(* Logix 5000 project; controller eNod4TSample vendor 1 type 14 code 106 rev 28.12; software revision 28.00 *)

TASK MainTask (continuous, watchdog 500 ms) : MainProgram

MODULES
   Local : vendor 1 type 14 code 106 (Compact 0, rev 28.12)
      Scale1 : vendor 1354 type 100 code 100 (Ethernet 192.168.0.100, rev 2.1, StandardDataDriven RPI 20 ms)
END_MODULES

TYPE TeNod4TCAL :   // Calibration datas class 0x65
STRUCT
   MeasureRange : DINT;
   CalibSegments : INT;
   CalibSegment1 : DINT;
   CalibSegment2 : DINT;
   CalibSegment3 : DINT;
   SensorSens : DINT;
   Step : INT;
   CalibZero : DINT;
   CalibCoeff1 : REAL;
   CalibCoeff2 : REAL;
   CalibCoeff3 : REAL;
   CalibSpanCorr : DINT;
   gValueCalib : DINT;
   gValueLocal : DINT;
   ZeroOffset : DINT;
   FixedTare : DINT;
   SensorRef : DINT;
   SensorTol : INT;
END_STRUCT
END_TYPE

TYPE TeNod4TCYCIN :
STRUCT
   eNodCounter : DINT;
   MeasureStatus : TeNod4TStatus;
   Gross : DINT;
   Tare : DINT;
   Net : DINT;
   ADCPoints : DINT;
   CommandEcho : INT;
   Response : INT;
END_STRUCT
END_TYPE

TYPE TeNod4TCYCOUT :
STRUCT
   Command : INT;
END_STRUCT
END_TYPE

TYPE TeNod4TDatas :   // Global datas for eNod4 and functions
STRUCT
   CYCIN : TeNod4TCYCIN;
   CYCOUT : TeNod4TCYCOUT;
   CAL : TeNod4TCAL;
   FIL : TeNod4TFILTER;
   LEGAL : TeNod4TLEGAL;
   IOCFG : TeNod4TIOCFG;
   MSGBuffer : SINT[100];   // Internaly used for explicit messages
   MSGGroup : INT;   // Current message group of last comm error
   MSGClass : INT;   // Current CIP class of last comm error
   MSGAttribute : INT;   // Current CIP attribute of last comm error
   MSGError : INT;   // Last MSG error
   MSGErrorEx : DINT;   // Last MSG extendeed error
   INT : TeNod4TInternal;   // Internal usage
END_STRUCT
END_TYPE

TYPE TeNod4TFILTER :
STRUCT
   ADConversionRate : INT;
   Activation : SINT;
   LowPassOrder : SINT;
   LowPassFreq : INT;
   BandCutHigh : INT;
   BandCutLow : INT;
END_STRUCT
END_TYPE

TYPE TeNod4TInternal :   // For internal usage between blocs, do not use
STRUCT
   CALRead : BOOL;
   CALWrite : BOOL;
   FILTERRead : BOOL;
   FILTERWrite : BOOL;
   CalibWrite : BOOL;
   LegelReadAll : BOOL;
   LegalWriteCfg : BOOL;
   LegalReadLastID : BOOL;
   LegalReadDSD : BOOL;
   LegalWriteID : BOOL;
   IOCFGRead : BOOL;
   IOCFGWrite : BOOL;
   Ready : BOOL;
   Done : BOOL;
   Error : BOOL;
   MSGError : BOOL;
   MSGCancel : BOOL;
   Command : INT;
END_STRUCT
END_TYPE

TYPE TeNod4TIOCFG :
STRUCT
   Input1Function : SINT;
   Input2Function : SINT;
   HoldingTime : INT;
   Output1Function : SINT;
   Output2Function : SINT;
   Output3Function : SINT;
   Output4Function : SINT;
   SetPoint1High : DINT;
   SetPoint1Low : DINT;
   SetPoint2High : DINT;
   SetPoint2Low : DINT;
   SetPoint3High : DINT;
   SetPoint3Low : DINT;
   SetPoint4High : DINT;
   SetPoint4Low : DINT;
   Setpoint12Function : SINT;
   Setpoint34Function : SINT;
END_STRUCT
END_TYPE

TYPE TeNod4TLEGAL :
STRUCT
   eNodVersion : INT;
   ModbusCfg : INT;
   LegalVersion : SINT;
   LegalSwitch : SINT;
   LegalCount : SINT;
   LegalChecksum : INT;
   ZeroConfig : INT;
   Stability : SINT;
   Decimal : SINT;
   Unit : SINT[4];
   DSDLastID : DINT;
   DSDOldestID : DINT;
   DSDCurrentID : DINT;
   DSDReadID : DINT;
   DSDReadNet : DINT;
   DSDResdTare : DINT;
   DSDReadStatus : INT;
   DSDReadChecksum : INT;
   HMIName : SINT[4];
END_STRUCT
END_TYPE

TYPE TeNod4TMSGElement :   // Internal use
STRUCT
   Class : SINT;
   Attribute : SINT;
   Offset : SINT;
   Length : SINT;
END_STRUCT
END_TYPE

TYPE TeNod4TStatus :
STRUCT
   Reserved : INT;
   b00Reserved : BOOL;
   b01Reserved : BOOL;
   b02ErrorCode0 : BOOL;
   b03ErrorCode1 : BOOL;
   b04NoMotion : BOOL;
   b05ZeroWeight : BOOL;
   b06EEPROMFailure : BOOL;
   b07Reserved : BOOL;
   b08Input1ON : BOOL;
   b09Input2ON : BOOL;
   b10Output1ON : BOOL;
   b11Output2ON : BOOL;
   b12Output3ON : BOOL;
   b13Output4ON : BOOL;
   b14TareActive : BOOL;
   b15Reservd : BOOL;
END_STRUCT
END_TYPE

ADD_ON_INSTRUCTION TeNod4TBlocBackupRestore   (* revision 1.1, vendor Scaime *)
VAR_IN_OUT
   Datas : TeNod4TDatas; {required}
END_VAR
VAR_INPUT
   Backup : BOOL; {visible}
   Restore : BOOL; {visible}
END_VAR
VAR_OUTPUT
   InProgress : BOOL; {visible}
   Done : BOOL; {visible}
   Error : BOOL; {visible}
END_VAR
VAR
   IntBackup : BOOL; {access None}
   IntRestore1 : BOOL; {access None}
   IntRestore2 : BOOL; {access None}
   IntRestore3 : BOOL; {access None}
   IntRestore4 : BOOL; {access None}
END_VAR

ROUTINE Logic   (* ladder *)
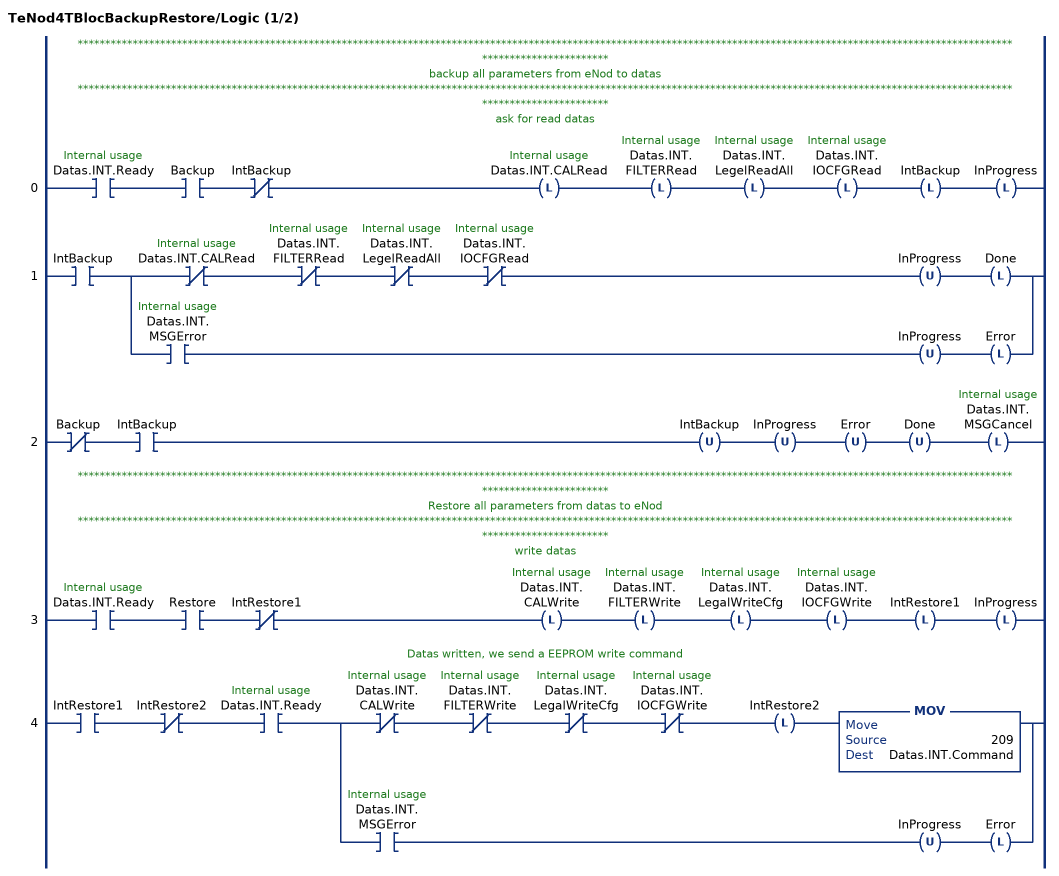
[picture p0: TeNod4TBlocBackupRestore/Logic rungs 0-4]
   // *************************************************************************************************************************************************************************************************
   // backup all parameters from eNod to datas
   // *************************************************************************************************************************************************************************************************
   // ask for read datas
   0: XIC(Datas.INT.Ready)XIC(Backup)XIO(IntBackup)OTL(Datas.INT.CALRead)OTL(Datas.INT.FILTERRead)OTL(Datas.INT.LegelReadAll)OTL(Datas.INT.IOCFGRead)OTL(IntBackup)OTL(InProgress);
   1: XIC(IntBackup)[XIO(Datas.INT.CALRead) XIO(Datas.INT.FILTERRead) XIO(Datas.INT.LegelReadAll) XIO(Datas.INT.IOCFGRead) OTU(InProgress) OTL(Done) ,XIC(Datas.INT.MSGError) OTU(InProgress) OTL(Error) ];
   2: XIO(Backup)XIC(IntBackup)OTU(IntBackup)OTU(InProgress)OTU(Error)OTU(Done)OTL(Datas.INT.MSGCancel);
   // *************************************************************************************************************************************************************************************************
   // Restore all parameters from datas to eNod
   // *************************************************************************************************************************************************************************************************
   // write datas
   3: XIC(Datas.INT.Ready)XIC(Restore)XIO(IntRestore1)OTL(Datas.INT.CALWrite)OTL(Datas.INT.FILTERWrite)OTL(Datas.INT.LegalWriteCfg)OTL(Datas.INT.IOCFGWrite)OTL(IntRestore1)OTL(InProgress);
   // Datas written, we send a EEPROM write command
   4: XIC(IntRestore1)XIO(IntRestore2)XIC(Datas.INT.Ready)[XIO(Datas.INT.CALWrite) XIO(Datas.INT.FILTERWrite) XIO(Datas.INT.LegalWriteCfg) XIO(Datas.INT.IOCFGWrite) OTL(IntRestore2) MOV(209,Datas.INT.Command) ,XIC(Datas.INT.MSGError) OTU(InProgress) OTL(Error) ];
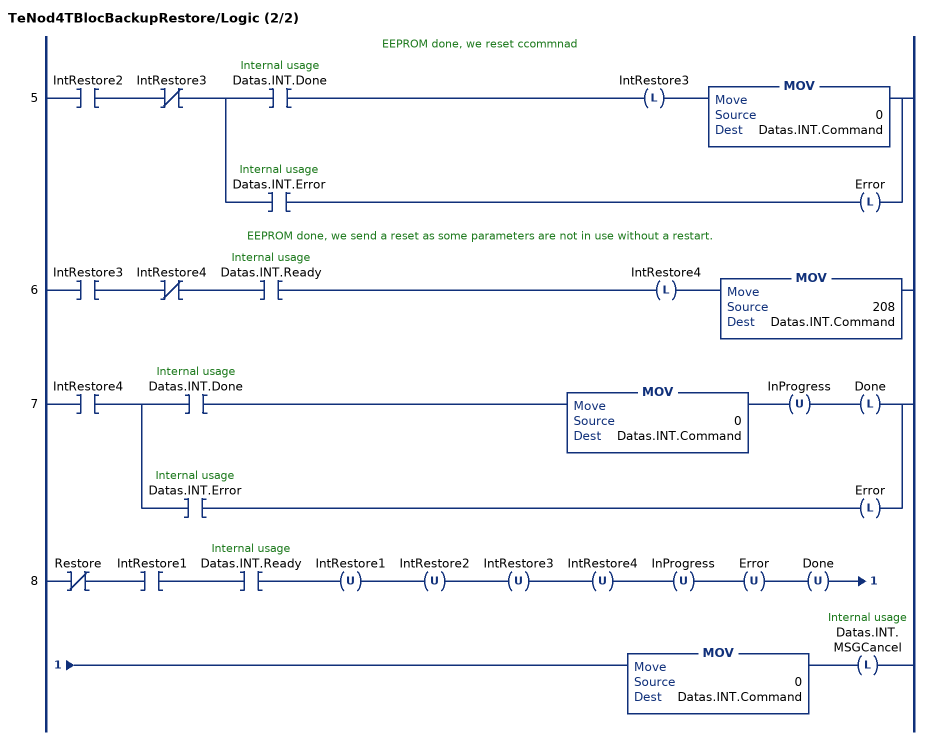
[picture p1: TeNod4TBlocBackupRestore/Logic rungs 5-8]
   // EEPROM done, we reset ccommnad
   5: XIC(IntRestore2)XIO(IntRestore3)[XIC(Datas.INT.Done) OTL(IntRestore3) MOV(0,Datas.INT.Command) ,XIC(Datas.INT.Error) OTL(Error) ];
   // EEPROM done, we send a reset as some parameters are not in use without a restart.
   6: XIC(IntRestore3)XIO(IntRestore4)XIC(Datas.INT.Ready)OTL(IntRestore4)MOV(208,Datas.INT.Command);
   7: XIC(IntRestore4)[XIC(Datas.INT.Done) MOV(0,Datas.INT.Command) OTU(InProgress) OTL(Done) ,XIC(Datas.INT.Error) OTL(Error) ];
   8: XIO(Restore)XIC(IntRestore1)XIC(Datas.INT.Ready)OTU(IntRestore1)OTU(IntRestore2)OTU(IntRestore3)OTU(IntRestore4)OTU(InProgress)OTU(Error)OTU(Done)MOV(0,Datas.INT.Command)OTL(Datas.INT.MSGCancel);
END_ROUTINE
END_ADD_ON_INSTRUCTION

ADD_ON_INSTRUCTION TeNod4TBlocCalibration   (* revision 1.0, vendor Scaime *)
VAR_IN_OUT
   Datas : TeNod4TDatas; {required}
END_VAR
VAR_INPUT
   NumSegment : INT := 1; {visible}
   ValSegment1 : DINT; {visible}
   ValSegment2 : DINT; {visible}
   ValSegment3 : DINT; {visible}
   Start : BOOL; {visible}
   Zero : BOOL; {visible}
   Segment1 : BOOL; {visible}
   Segment2 : BOOL; {visible}
   Segment3 : BOOL; {visible}
   Save : BOOL; {visible}
   Cancel : BOOL; {visible}
   Theorical : BOOL; {visible}
   ZeroAdjust : BOOL; {visible}
END_VAR
VAR_OUTPUT
   InProgress : BOOL; {visible}
   ZeroDone : BOOL; {visible}
   Seg1Done : BOOL; {visible}
   Seg2Done : BOOL; {visible}
   Seg3Done : BOOL; {visible}
   Complete : BOOL; {visible}
   Error : BOOL; {visible}
END_VAR
VAR
   IntStart1 : BOOL; {access None}
   IntStart2 : BOOL; {access None}
   IntZero : BOOL; {access None}
   IntSeg1 : BOOL; {access None}
   IntSeg2 : BOOL; {access None}
   IntSeg3 : BOOL; {access None}
   IntSave1 : BOOL; {access None}
   IntSave2 : BOOL; {access None}
   IntCancel : BOOL; {access None}
   IntTheo : BOOL; {access None}
   IntZeroA : BOOL; {access None}
   IntSeg1B : BOOL; {access None}
   IntSeg2B : BOOL; {access None}
   IntSeg3B : BOOL; {access None}
END_VAR

ROUTINE Logic   (* ladder *)
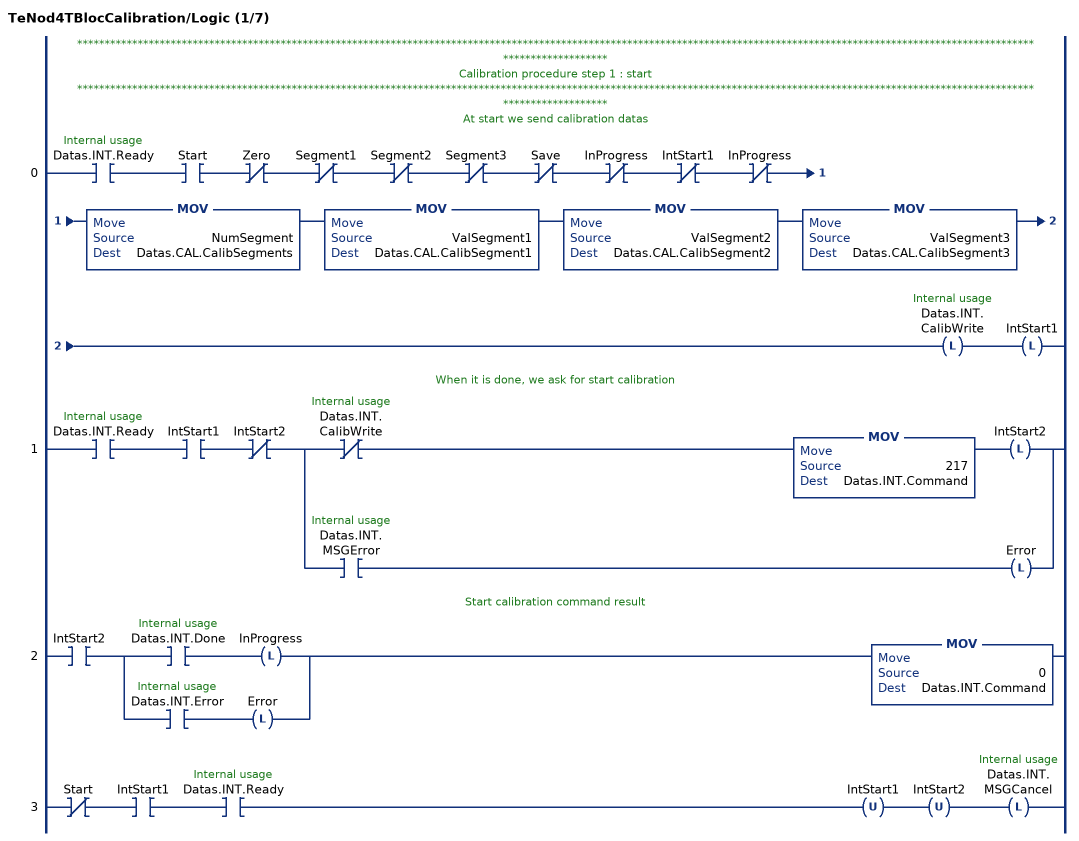
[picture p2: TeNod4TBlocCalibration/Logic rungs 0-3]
   // *************************************************************************************************************************************************************************************************
   // Calibration procedure step 1 : start
   // *************************************************************************************************************************************************************************************************
   // At start we send calibration datas
   0: XIC(Datas.INT.Ready)XIC(Start)XIO(Zero)XIO(Segment1)XIO(Segment2)XIO(Segment3)XIO(Save)XIO(InProgress)XIO(IntStart1)XIO(InProgress)MOV(NumSegment,Datas.CAL.CalibSegments)MOV(ValSegment1,Datas.CAL.CalibSegment1)MOV(ValSegment2,Datas.CAL.CalibSegment2)MOV(ValSegment3,Datas.CAL.CalibSegment3)OTL(Datas.INT.CalibWrite)OTL(IntStart1);
   // When it is done, we ask for start calibration
   1: XIC(Datas.INT.Ready)XIC(IntStart1)XIO(IntStart2)[XIO(Datas.INT.CalibWrite) MOV(217,Datas.INT.Command) OTL(IntStart2) ,XIC(Datas.INT.MSGError) OTL(Error) ];
   // Start calibration command result
   2: XIC(IntStart2)[XIC(Datas.INT.Done) OTL(InProgress) ,XIC(Datas.INT.Error) OTL(Error) ]MOV(0,Datas.INT.Command);
   3: XIO(Start)XIC(IntStart1)XIC(Datas.INT.Ready)OTU(IntStart1)OTU(IntStart2)OTL(Datas.INT.MSGCancel);
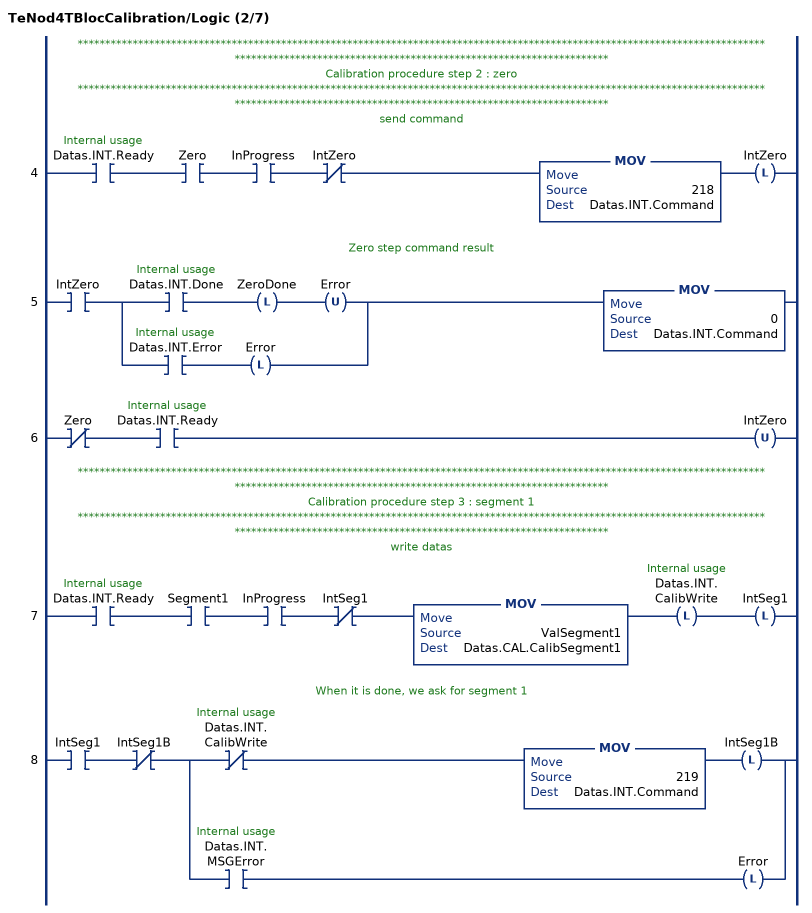
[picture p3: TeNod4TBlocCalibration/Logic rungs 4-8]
   // *************************************************************************************************************************************************************************************************
   // Calibration procedure step 2 : zero
   // *************************************************************************************************************************************************************************************************
   // send command
   4: XIC(Datas.INT.Ready)XIC(Zero)XIC(InProgress)XIO(IntZero)MOV(218,Datas.INT.Command)OTL(IntZero);
   // Zero step command result
   5: XIC(IntZero)[XIC(Datas.INT.Done) OTL(ZeroDone) OTU(Error) ,XIC(Datas.INT.Error) OTL(Error) ]MOV(0,Datas.INT.Command);
   6: XIO(Zero)XIC(Datas.INT.Ready)OTU(IntZero);
   // *************************************************************************************************************************************************************************************************
   // Calibration procedure step 3 : segment 1
   // *************************************************************************************************************************************************************************************************
   // write datas
   7: XIC(Datas.INT.Ready)XIC(Segment1)XIC(InProgress)XIO(IntSeg1)MOV(ValSegment1,Datas.CAL.CalibSegment1)OTL(Datas.INT.CalibWrite)OTL(IntSeg1);
   // When it is done, we ask for segment 1
   8: XIC(IntSeg1)XIO(IntSeg1B)[XIO(Datas.INT.CalibWrite) MOV(219,Datas.INT.Command) OTL(IntSeg1B) ,XIC(Datas.INT.MSGError) OTL(Error) ];
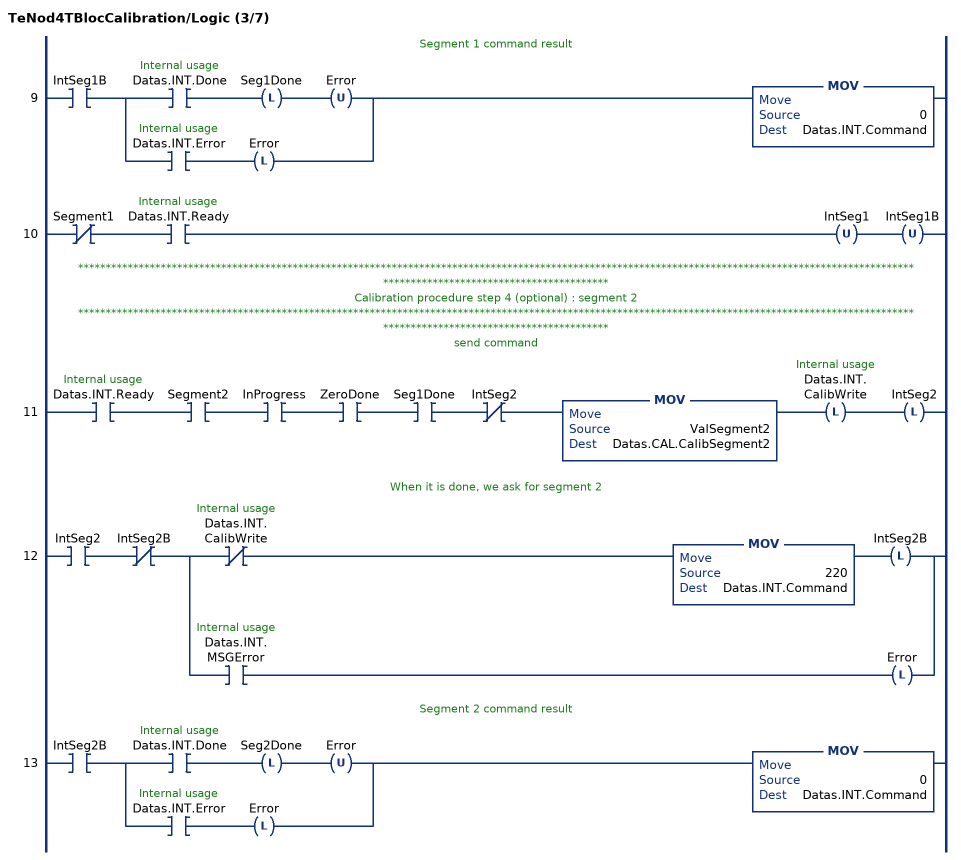
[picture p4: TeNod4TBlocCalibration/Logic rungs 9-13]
   // Segment 1 command result
   9: XIC(IntSeg1B)[XIC(Datas.INT.Done) OTL(Seg1Done) OTU(Error) ,XIC(Datas.INT.Error) OTL(Error) ]MOV(0,Datas.INT.Command);
   10: XIO(Segment1)XIC(Datas.INT.Ready)OTU(IntSeg1)OTU(IntSeg1B);
   // *************************************************************************************************************************************************************************************************
   // Calibration procedure step 4 (optional) : segment 2
   // *************************************************************************************************************************************************************************************************
   // send command
   11: XIC(Datas.INT.Ready)XIC(Segment2)XIC(InProgress)XIC(ZeroDone)XIC(Seg1Done)XIO(IntSeg2)MOV(ValSegment2,Datas.CAL.CalibSegment2)OTL(Datas.INT.CalibWrite)OTL(IntSeg2);
   // When it is done, we ask for segment 2
   12: XIC(IntSeg2)XIO(IntSeg2B)[XIO(Datas.INT.CalibWrite) MOV(220,Datas.INT.Command) OTL(IntSeg2B) ,XIC(Datas.INT.MSGError) OTL(Error) ];
   // Segment 2 command result
   13: XIC(IntSeg2B)[XIC(Datas.INT.Done) OTL(Seg2Done) OTU(Error) ,XIC(Datas.INT.Error) OTL(Error) ]MOV(0,Datas.INT.Command);
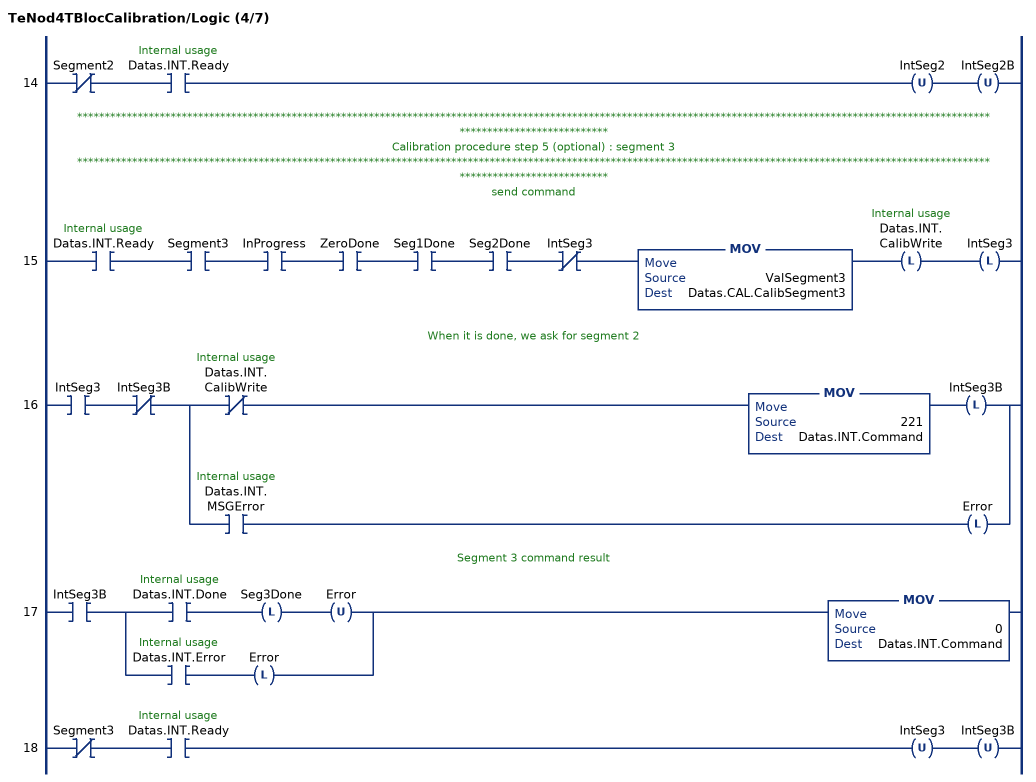
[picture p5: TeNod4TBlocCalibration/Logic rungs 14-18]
   14: XIO(Segment2)XIC(Datas.INT.Ready)OTU(IntSeg2)OTU(IntSeg2B);
   // *************************************************************************************************************************************************************************************************
   // Calibration procedure step 5 (optional) : segment 3
   // *************************************************************************************************************************************************************************************************
   // send command
   15: XIC(Datas.INT.Ready)XIC(Segment3)XIC(InProgress)XIC(ZeroDone)XIC(Seg1Done)XIC(Seg2Done)XIO(IntSeg3)MOV(ValSegment3,Datas.CAL.CalibSegment3)OTL(Datas.INT.CalibWrite)OTL(IntSeg3);
   // When it is done, we ask for segment 2
   16: XIC(IntSeg3)XIO(IntSeg3B)[XIO(Datas.INT.CalibWrite) MOV(221,Datas.INT.Command) OTL(IntSeg3B) ,XIC(Datas.INT.MSGError) OTL(Error) ];
   // Segment 3 command result
   17: XIC(IntSeg3B)[XIC(Datas.INT.Done) OTL(Seg3Done) OTU(Error) ,XIC(Datas.INT.Error) OTL(Error) ]MOV(0,Datas.INT.Command);
   18: XIO(Segment3)XIC(Datas.INT.Ready)OTU(IntSeg3)OTU(IntSeg3B);
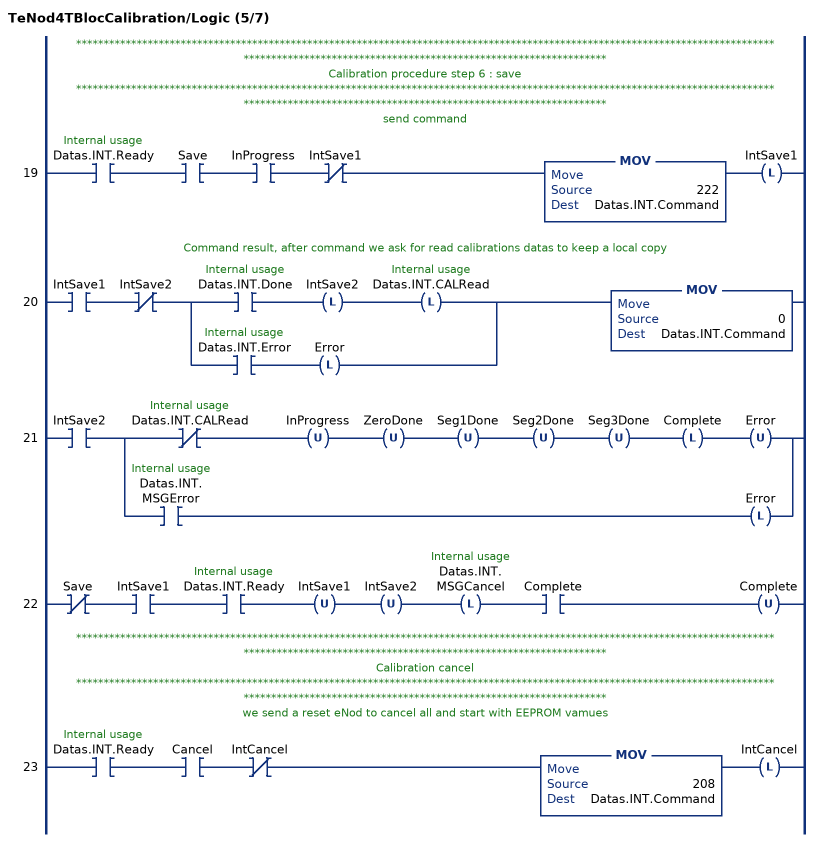
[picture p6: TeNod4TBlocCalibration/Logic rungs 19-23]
   // *************************************************************************************************************************************************************************************************
   // Calibration procedure step 6 : save
   // *************************************************************************************************************************************************************************************************
   // send command
   19: XIC(Datas.INT.Ready)XIC(Save)XIC(InProgress)XIO(IntSave1)MOV(222,Datas.INT.Command)OTL(IntSave1);
   // Command result, after command we ask for read calibrations datas to keep a local copy
   20: XIC(IntSave1)XIO(IntSave2)[XIC(Datas.INT.Done) OTL(IntSave2) OTL(Datas.INT.CALRead) ,XIC(Datas.INT.Error) OTL(Error) ]MOV(0,Datas.INT.Command);
   21: XIC(IntSave2)[XIO(Datas.INT.CALRead) OTU(InProgress) OTU(ZeroDone) OTU(Seg1Done) OTU(Seg2Done) OTU(Seg3Done) OTL(Complete) OTU(Error) ,XIC(Datas.INT.MSGError) OTL(Error) ];
   22: XIO(Save)XIC(IntSave1)XIC(Datas.INT.Ready)OTU(IntSave1)OTU(IntSave2)OTL(Datas.INT.MSGCancel)XIC(Complete)OTU(Complete);
   // *************************************************************************************************************************************************************************************************
   // Calibration cancel
   // *************************************************************************************************************************************************************************************************
   // we send a reset eNod to cancel all and start with EEPROM vamues
   23: XIC(Datas.INT.Ready)XIC(Cancel)XIO(IntCancel)MOV(208,Datas.INT.Command)OTL(IntCancel);
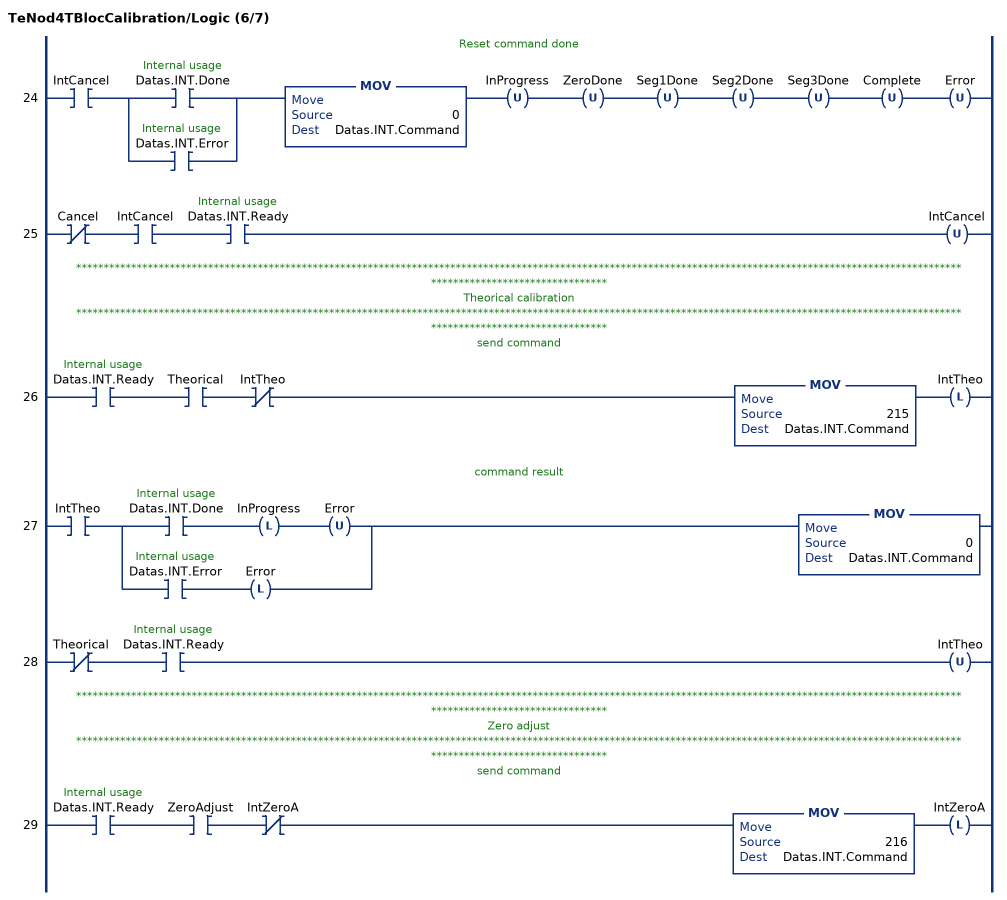
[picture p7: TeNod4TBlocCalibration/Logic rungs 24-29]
   // Reset command done
   24: XIC(IntCancel)[XIC(Datas.INT.Done) ,XIC(Datas.INT.Error) ]MOV(0,Datas.INT.Command)OTU(InProgress)OTU(ZeroDone)OTU(Seg1Done)OTU(Seg2Done)OTU(Seg3Done)OTU(Complete)OTU(Error);
   25: XIO(Cancel)XIC(IntCancel)XIC(Datas.INT.Ready)OTU(IntCancel);
   // *************************************************************************************************************************************************************************************************
   // Theorical calibration
   // *************************************************************************************************************************************************************************************************
   // send command
   26: XIC(Datas.INT.Ready)XIC(Theorical)XIO(IntTheo)MOV(215,Datas.INT.Command)OTL(IntTheo);
   // command result
   27: XIC(IntTheo)[XIC(Datas.INT.Done) OTL(InProgress) OTU(Error) ,XIC(Datas.INT.Error) OTL(Error) ]MOV(0,Datas.INT.Command);
   28: XIO(Theorical)XIC(Datas.INT.Ready)OTU(IntTheo);
   // *************************************************************************************************************************************************************************************************
   // Zero adjust
   // *************************************************************************************************************************************************************************************************
   // send command
   29: XIC(Datas.INT.Ready)XIC(ZeroAdjust)XIO(IntZeroA)MOV(216,Datas.INT.Command)OTL(IntZeroA);
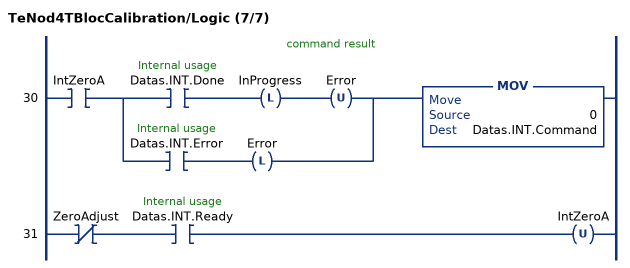
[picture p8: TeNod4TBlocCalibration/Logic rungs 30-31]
   // command result
   30: XIC(IntZeroA)[XIC(Datas.INT.Done) OTL(InProgress) OTU(Error) ,XIC(Datas.INT.Error) OTL(Error) ]MOV(0,Datas.INT.Command);
   31: XIO(ZeroAdjust)XIC(Datas.INT.Ready)OTU(IntZeroA);
END_ROUTINE
END_ADD_ON_INSTRUCTION

ADD_ON_INSTRUCTION TeNod4TBlocFilters   (* revision 1.1, vendor Scaime *)
VAR_IN_OUT
   Datas : TeNod4TDatas; {required}
END_VAR
VAR_INPUT
   Read : BOOL; {visible}
   Write : BOOL; {visible}
END_VAR
VAR_OUTPUT
   InProgress : BOOL; {visible}
   Done : BOOL; {visible}
   Error : BOOL; {visible}
END_VAR
VAR
   IntRead : BOOL; {access None}
   IntWrite1 : BOOL; {access None}
   IntWrite2 : BOOL; {access None}
END_VAR

ROUTINE Logic   (* ladder *)
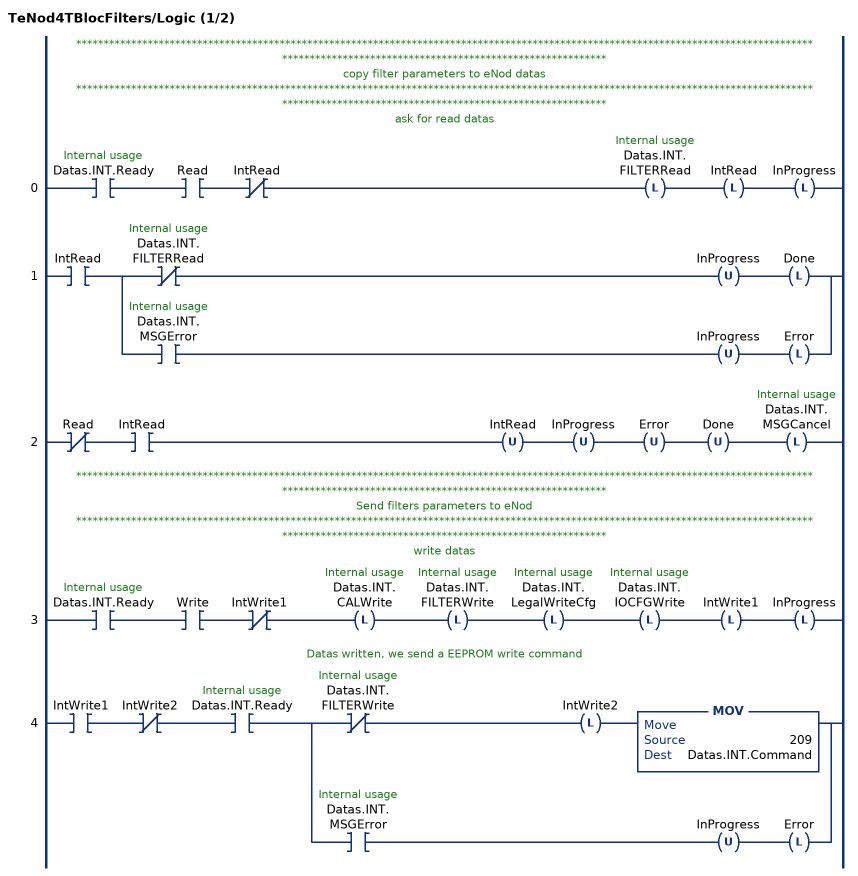
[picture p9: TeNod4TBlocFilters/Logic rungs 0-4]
   // *************************************************************************************************************************************************************************************************
   // copy filter parameters to eNod datas
   // *************************************************************************************************************************************************************************************************
   // ask for read datas
   0: XIC(Datas.INT.Ready)XIC(Read)XIO(IntRead)OTL(Datas.INT.FILTERRead)OTL(IntRead)OTL(InProgress);
   1: XIC(IntRead)[XIO(Datas.INT.FILTERRead) OTU(InProgress) OTL(Done) ,XIC(Datas.INT.MSGError) OTU(InProgress) OTL(Error) ];
   2: XIO(Read)XIC(IntRead)OTU(IntRead)OTU(InProgress)OTU(Error)OTU(Done)OTL(Datas.INT.MSGCancel);
   // *************************************************************************************************************************************************************************************************
   // Send filters parameters to eNod
   // *************************************************************************************************************************************************************************************************
   // write datas
   3: XIC(Datas.INT.Ready)XIC(Write)XIO(IntWrite1)OTL(Datas.INT.CALWrite)OTL(Datas.INT.FILTERWrite)OTL(Datas.INT.LegalWriteCfg)OTL(Datas.INT.IOCFGWrite)OTL(IntWrite1)OTL(InProgress);
   // Datas written, we send a EEPROM write command
   4: XIC(IntWrite1)XIO(IntWrite2)XIC(Datas.INT.Ready)[XIO(Datas.INT.FILTERWrite) OTL(IntWrite2) MOV(209,Datas.INT.Command) ,XIC(Datas.INT.MSGError) OTU(InProgress) OTL(Error) ];
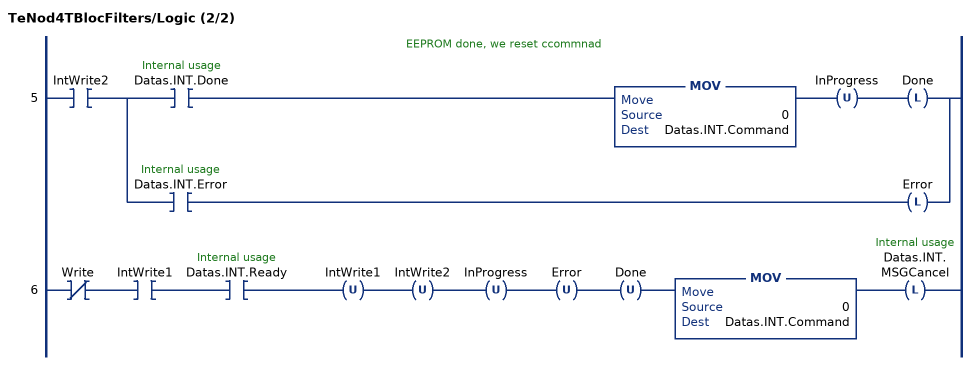
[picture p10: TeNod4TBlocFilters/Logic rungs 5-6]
   // EEPROM done, we reset ccommnad
   5: XIC(IntWrite2)[XIC(Datas.INT.Done) MOV(0,Datas.INT.Command) OTU(InProgress) OTL(Done) ,XIC(Datas.INT.Error) OTL(Error) ];
   6: XIO(Write)XIC(IntWrite1)XIC(Datas.INT.Ready)OTU(IntWrite1)OTU(IntWrite2)OTU(InProgress)OTU(Error)OTU(Done)MOV(0,Datas.INT.Command)OTL(Datas.INT.MSGCancel);
END_ROUTINE
END_ADD_ON_INSTRUCTION

ADD_ON_INSTRUCTION TeNod4TBlocLegal   (* revision 1.1, vendor Scaime *)
VAR_IN_OUT
   Datas : TeNod4TDatas; {required}
END_VAR
VAR_INPUT
   CaptureRead : BOOL; {visible}
   CaptureOnly : BOOL; {visible}
   RequestedID : DINT; {visible}
   Read : BOOL; {visible}
END_VAR
VAR_OUTPUT
   InProgress : BOOL; {visible}
   Done : BOOL; {visible}
   Error : BOOL; {visible}
   CapturedID : DINT; {access Read Only, visible}
END_VAR
VAR
   IntCapture1 : BOOL; {access None}
   IntCapture2 : BOOL; {access None}
   IntCapture3 : BOOL; {access None}
   ReadSeq : BOOL; {access None}
   ReadSeq1 : BOOL; {access None}
   ReadSeq2 : BOOL; {access None}
   ReadSeq3 : BOOL; {access None}
   ReadSeqDone : BOOL; {access None}
   IntRead1 : BOOL; {access None}
END_VAR

ROUTINE Logic   (* ladder *)
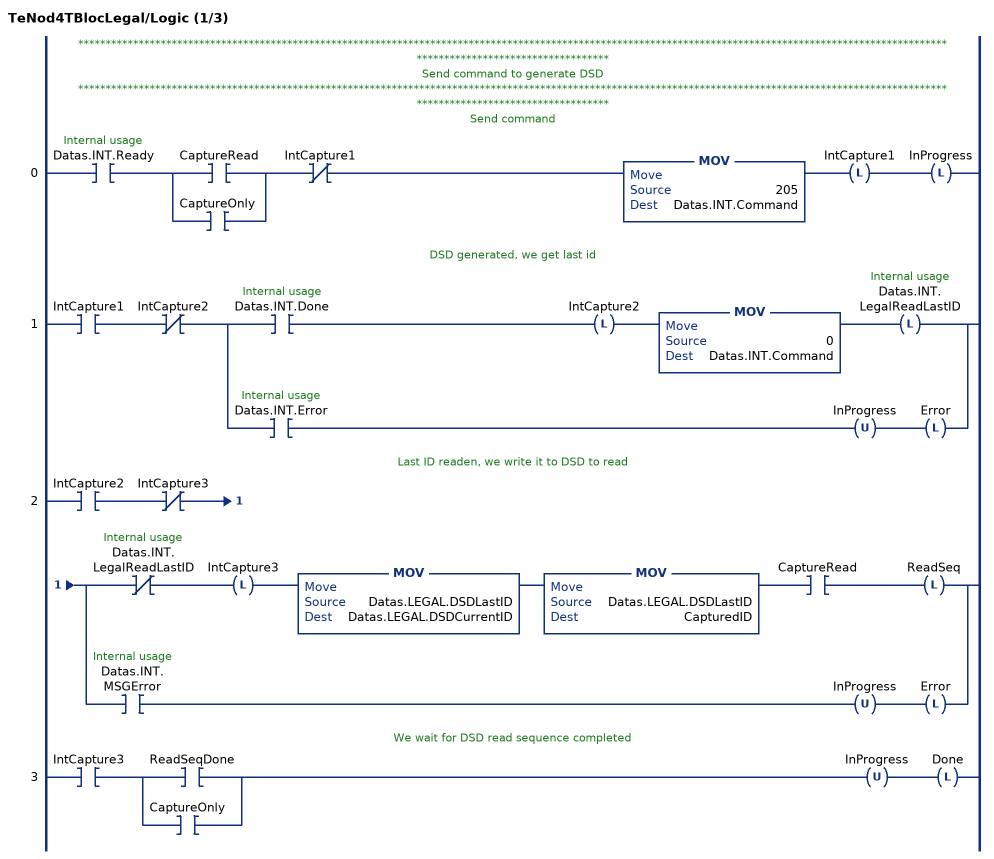
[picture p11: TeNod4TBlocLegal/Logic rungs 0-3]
   // *************************************************************************************************************************************************************************************************
   // Send command to generate DSD
   // *************************************************************************************************************************************************************************************************
   // Send command
   0: XIC(Datas.INT.Ready)[XIC(CaptureRead) ,XIC(CaptureOnly) ]XIO(IntCapture1)MOV(205,Datas.INT.Command)OTL(IntCapture1)OTL(InProgress);
   // DSD generated, we get last id
   1: XIC(IntCapture1)XIO(IntCapture2)[XIC(Datas.INT.Done) OTL(IntCapture2) MOV(0,Datas.INT.Command) OTL(Datas.INT.LegalReadLastID) ,XIC(Datas.INT.Error) OTU(InProgress) OTL(Error) ];
   // Last ID readen, we write it to DSD to read
   2: XIC(IntCapture2)XIO(IntCapture3)[XIO(Datas.INT.LegalReadLastID) OTL(IntCapture3) MOV(Datas.LEGAL.DSDLastID,Datas.LEGAL.DSDCurrentID) MOV(Datas.LEGAL.DSDLastID,CapturedID) XIC(CaptureRead) OTL(ReadSeq) ,XIC(Datas.INT.MSGError) OTU(InProgress) OTL(Error) ];
   // We wait for DSD read sequence completed
   3: XIC(IntCapture3)[XIC(ReadSeqDone) ,XIC(CaptureOnly) ]OTU(InProgress)OTL(Done);
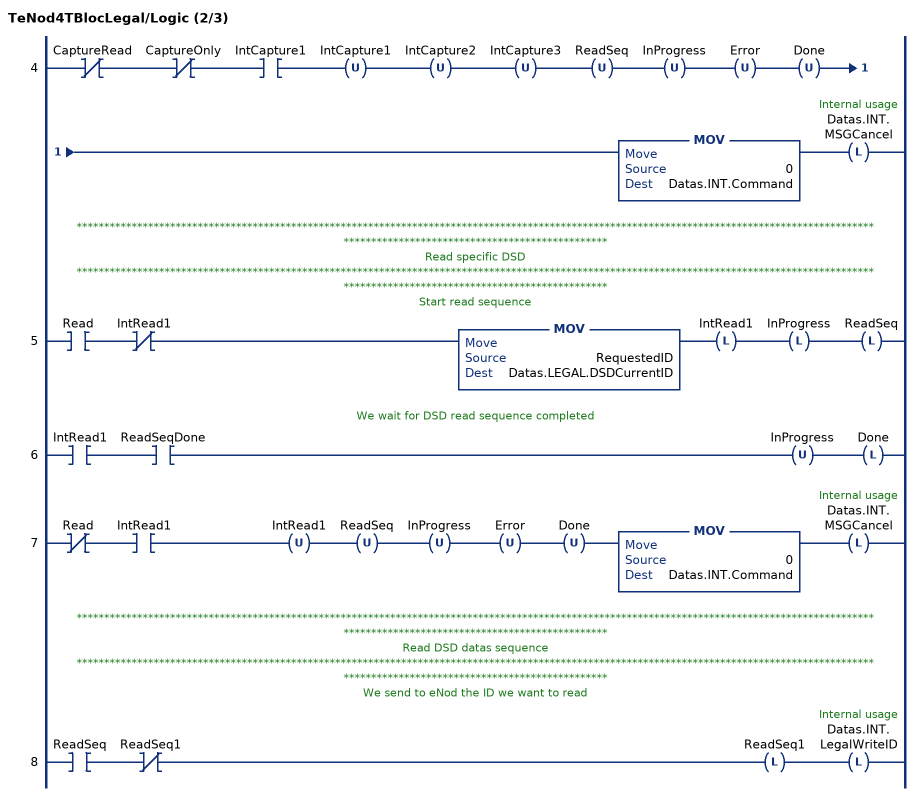
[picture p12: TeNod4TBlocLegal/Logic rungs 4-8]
   4: XIO(CaptureRead)XIO(CaptureOnly)XIC(IntCapture1)OTU(IntCapture1)OTU(IntCapture2)OTU(IntCapture3)OTU(ReadSeq)OTU(InProgress)OTU(Error)OTU(Done)MOV(0,Datas.INT.Command)OTL(Datas.INT.MSGCancel);
   // *************************************************************************************************************************************************************************************************
   // Read specific DSD
   // *************************************************************************************************************************************************************************************************
   // Start read sequence
   5: XIC(Read)XIO(IntRead1)MOV(RequestedID,Datas.LEGAL.DSDCurrentID)OTL(IntRead1)OTL(InProgress)OTL(ReadSeq);
   // We wait for DSD read sequence completed
   6: XIC(IntRead1)XIC(ReadSeqDone)OTU(InProgress)OTL(Done);
   7: XIO(Read)XIC(IntRead1)OTU(IntRead1)OTU(ReadSeq)OTU(InProgress)OTU(Error)OTU(Done)MOV(0,Datas.INT.Command)OTL(Datas.INT.MSGCancel);
   // *************************************************************************************************************************************************************************************************
   // Read DSD datas sequence
   // *************************************************************************************************************************************************************************************************
   // We send to eNod the ID we want to read
   8: XIC(ReadSeq)XIO(ReadSeq1)OTL(ReadSeq1)OTL(Datas.INT.LegalWriteID);
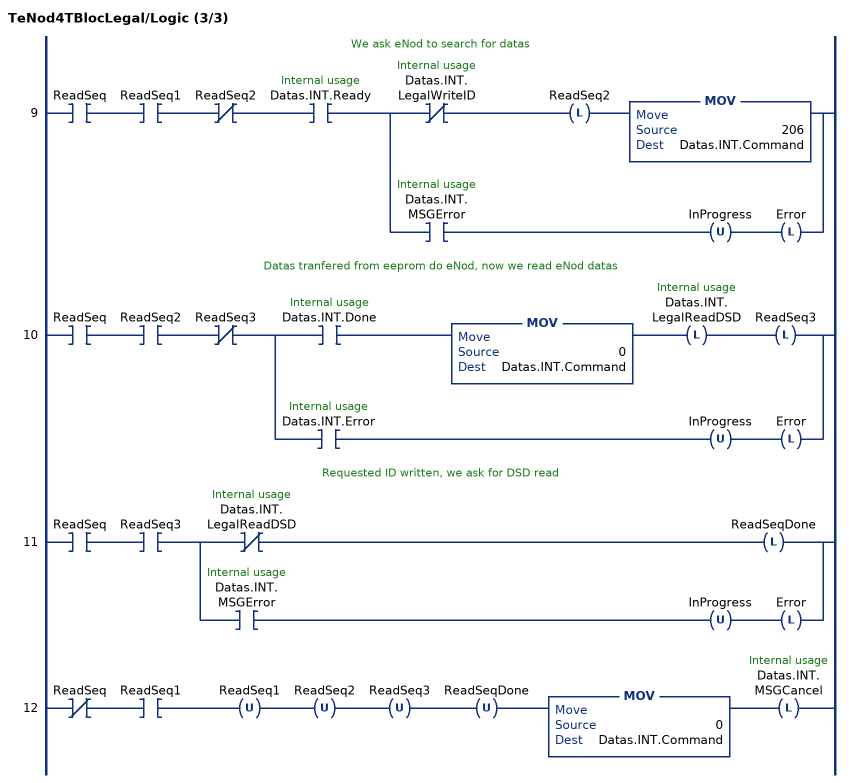
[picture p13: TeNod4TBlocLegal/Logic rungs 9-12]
   // We ask eNod to search for datas
   9: XIC(ReadSeq)XIC(ReadSeq1)XIO(ReadSeq2)XIC(Datas.INT.Ready)[XIO(Datas.INT.LegalWriteID) OTL(ReadSeq2) MOV(206,Datas.INT.Command) ,XIC(Datas.INT.MSGError) OTU(InProgress) OTL(Error) ];
   // Datas tranfered from eeprom do eNod, now we read eNod datas
   10: XIC(ReadSeq)XIC(ReadSeq2)XIO(ReadSeq3)[XIC(Datas.INT.Done) MOV(0,Datas.INT.Command) OTL(Datas.INT.LegalReadDSD) OTL(ReadSeq3) ,XIC(Datas.INT.Error) OTU(InProgress) OTL(Error) ];
   // Requested ID written, we ask for DSD read
   11: XIC(ReadSeq)XIC(ReadSeq3)[XIO(Datas.INT.LegalReadDSD) OTL(ReadSeqDone) ,XIC(Datas.INT.MSGError) OTU(InProgress) OTL(Error) ];
   12: XIO(ReadSeq)XIC(ReadSeq1)OTU(ReadSeq1)OTU(ReadSeq2)OTU(ReadSeq3)OTU(ReadSeqDone)MOV(0,Datas.INT.Command)OTL(Datas.INT.MSGCancel);
END_ROUTINE
END_ADD_ON_INSTRUCTION

ADD_ON_INSTRUCTION TeNod4TBlocMain   (* revision 1.1, vendor Scaime *)
VAR_IN_OUT
   Datas : TeNod4TDatas; {required}
   DatasIN : SINT[28]; {required}
   DatasOUT : SINT[2]; {required}
   MsgRead : MESSAGE; {required}
   MsgWrite : MESSAGE; {required}
END_VAR
VAR_INPUT
   Zero : BOOL; {visible}
   Tare : BOOL; {visible}
   ResetTare : BOOL; {visible}
   Command : INT; {visible}
END_VAR
VAR_OUTPUT
   Ready : BOOL; {access Read Only, visible}
   Run : BOOL; {access Read Only, visible}
   Done : BOOL; {visible}
   Error : BOOL; {visible}
   Timeout : BOOL; {access Read Only, visible}
END_VAR
VAR_INPUT
   StabWeight : DINT; {visible}
   StabTime : DINT; {visible}
END_VAR
VAR_OUTPUT
   Stability : BOOL; {visible}
END_VAR
VAR
   LoopRRun : BOOL; {access None}
   LoopAttr : INT; {access None}
   LoopDec : INT := 64; {access None}
   LoopLen : INT := 2; {access None}
   LoopMode : INT; {access None}
   MemCommand : INT; {access None}
   LoopIndex : DINT; {access None}
   LoopEdge : BOOL; {access None}
   LoopRStart : BOOL; {access None}
   LoopRStartEdge : BOOL; {access None}
   LoopRSend : BOOL; {access None}
   IntBuffer : SINT[256]; {access None}
   FirstRun : BOOL; {access None}
   MSGTabCal : TeNod4TMSGElement[20]; {access None}
   LoopTab : TeNod4TMSGElement[50]; {access None}
   MSGTabFilter : TeNod4TMSGElement[10]; {access None}
   LoopRDone : BOOL; {access None}
   CommandEX : BOOL; {access None}
   LoopWStart : BOOL; {access None}
   LoopWStartEdge : BOOL; {access None}
   LoopWRun : BOOL; {access None}
   LoopWSend : BOOL; {access None}
   LoopWDone : BOOL; {access None}
   MSGTabCalib : TeNod4TMSGElement[10] := ([0].Class := 101, [0].Attribute := 2, [0].Offset := 4, [0].Length := 2, [1].Class := 101, [1].Attribute := 3, [1].Offset := 8, [1].Length := 4, [2].Class := 101, [2].Attribute := 4, [2].Offset := 12, [2].Length := 4, [3].Class := 101, [3].Attribute := 5, [3].Offset := 16, [3].Length := 4); {access None}
   TimerReset : TIMER := (PRE := 3000); {access None}
   MSGTabLegalRAll : TeNod4TMSGElement[25]; {access None}
   MSGTabLegalWCfg : TeNod4TMSGElement[10] := ([0].Class := 100, [0].Attribute := 7, [0].Offset := 10, [0].Length := 2, [1].Class := 100, [1].Attribute := 8, [1].Offset := 12, [1].Length := 2, [2].Class := 100, [2].Attribute := 9, [2].Offset := 16, [2].Length := 4, [3].Class := 100, [3].Attribute := 21, [3].Offset := 48, [3].Length := 4); {access None}
   MSGTabLegalRID : TeNod4TMSGElement[2] := ([0].Class := 100, [0].Attribute := 13, [0].Length := 4); {access None}
   MSGTabLegalWID : TeNod4TMSGElement[2] := ([0].Class := 100, [0].Attribute := 15, [0].Length := 4); {access None}
   MSGTabLegalDSD : TeNod4TMSGElement[6]; {access None}
   MemCounter : DINT; {access None}
   TimerOut : TIMER := (PRE := 200); {access None}
   MSGTabIO : TeNod4TMSGElement[20]; {access None}
   TimerStab : TIMER; {access None}
   MemNet : DINT; {access None}
   StabOK : BOOL; {access None}
END_VAR

ROUTINE Logic   (* ladder *)
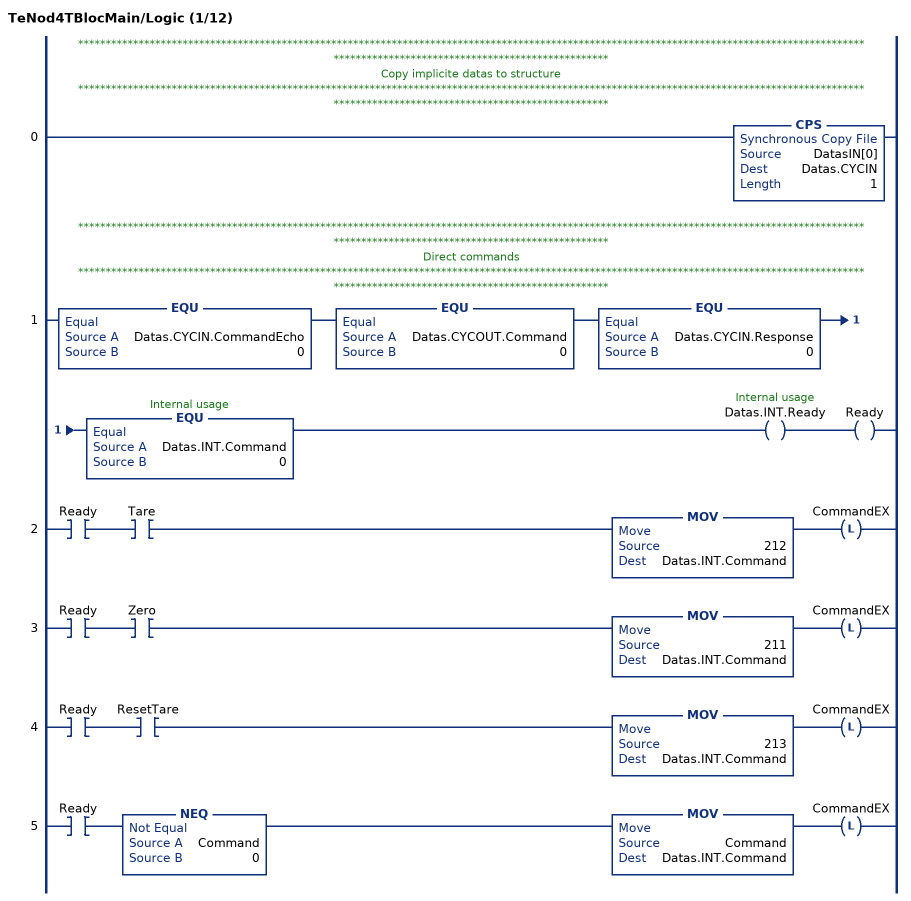
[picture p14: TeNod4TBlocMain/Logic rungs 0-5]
   // *************************************************************************************************************************************************************************************************
   // Copy implicite datas to structure
   // *************************************************************************************************************************************************************************************************
   0: CPS(DatasIN[0],Datas.CYCIN,1);
   // *************************************************************************************************************************************************************************************************
   // Direct commands
   // *************************************************************************************************************************************************************************************************
   1: EQU(Datas.CYCIN.CommandEcho,0)EQU(Datas.CYCOUT.Command,0)EQU(Datas.CYCIN.Response,0)EQU(Datas.INT.Command,0)OTE(Datas.INT.Ready)OTE(Ready);
   2: XIC(Ready)XIC(Tare)MOV(212,Datas.INT.Command)OTL(CommandEX);
   3: XIC(Ready)XIC(Zero)MOV(211,Datas.INT.Command)OTL(CommandEX);
   4: XIC(Ready)XIC(ResetTare)MOV(213,Datas.INT.Command)OTL(CommandEX);
   5: XIC(Ready)NEQ(Command,0)MOV(Command,Datas.INT.Command)OTL(CommandEX);
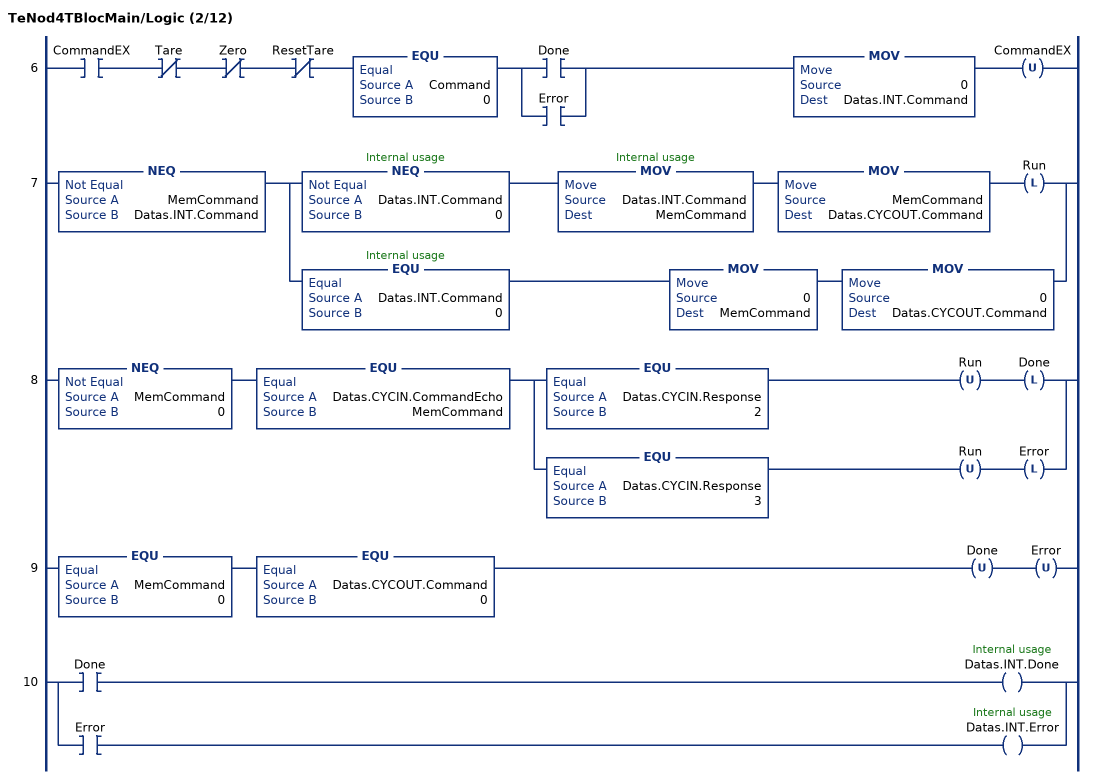
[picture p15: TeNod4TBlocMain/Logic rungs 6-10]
   6: XIC(CommandEX)XIO(Tare)XIO(Zero)XIO(ResetTare)EQU(Command,0)[XIC(Done) ,XIC(Error) ]MOV(0,Datas.INT.Command)OTU(CommandEX);
   7: NEQ(MemCommand,Datas.INT.Command)[NEQ(Datas.INT.Command,0) MOV(Datas.INT.Command,MemCommand) MOV(MemCommand,Datas.CYCOUT.Command) OTL(Run) ,EQU(Datas.INT.Command,0) MOV(0,MemCommand) MOV(0,Datas.CYCOUT.Command) ];
   8: NEQ(MemCommand,0)EQU(Datas.CYCIN.CommandEcho,MemCommand)[EQU(Datas.CYCIN.Response,2) OTU(Run) OTL(Done) ,EQU(Datas.CYCIN.Response,3) OTU(Run) OTL(Error) ];
   9: EQU(MemCommand,0)EQU(Datas.CYCOUT.Command,0)OTU(Done)OTU(Error);
   10: [XIC(Done) OTE(Datas.INT.Done) ,XIC(Error) OTE(Datas.INT.Error) ];
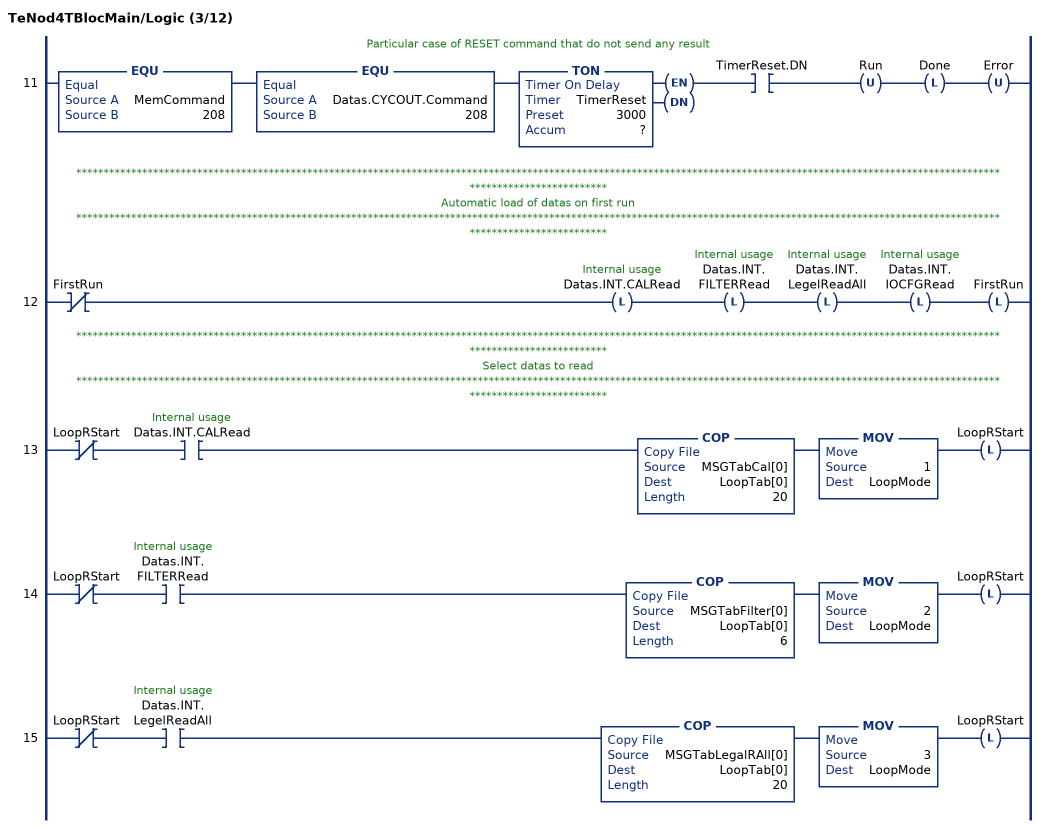
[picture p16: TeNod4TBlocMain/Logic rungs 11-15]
   // Particular case of RESET command that do not send any result
   11: EQU(MemCommand,208)EQU(Datas.CYCOUT.Command,208)TON(TimerReset,?,?)XIC(TimerReset.DN)OTU(Run)OTL(Done)OTU(Error);
   // *************************************************************************************************************************************************************************************************
   // Automatic load of datas on first run
   // *************************************************************************************************************************************************************************************************
   12: XIO(FirstRun)OTL(Datas.INT.CALRead)OTL(Datas.INT.FILTERRead)OTL(Datas.INT.LegelReadAll)OTL(Datas.INT.IOCFGRead)OTL(FirstRun);
   // *************************************************************************************************************************************************************************************************
   // Select datas to read
   // *************************************************************************************************************************************************************************************************
   13: XIO(LoopRStart)XIC(Datas.INT.CALRead)COP(MSGTabCal[0],LoopTab[0],20)MOV(1,LoopMode)OTL(LoopRStart);
   14: XIO(LoopRStart)XIC(Datas.INT.FILTERRead)COP(MSGTabFilter[0],LoopTab[0],6)MOV(2,LoopMode)OTL(LoopRStart);
   15: XIO(LoopRStart)XIC(Datas.INT.LegelReadAll)COP(MSGTabLegalRAll[0],LoopTab[0],20)MOV(3,LoopMode)OTL(LoopRStart);
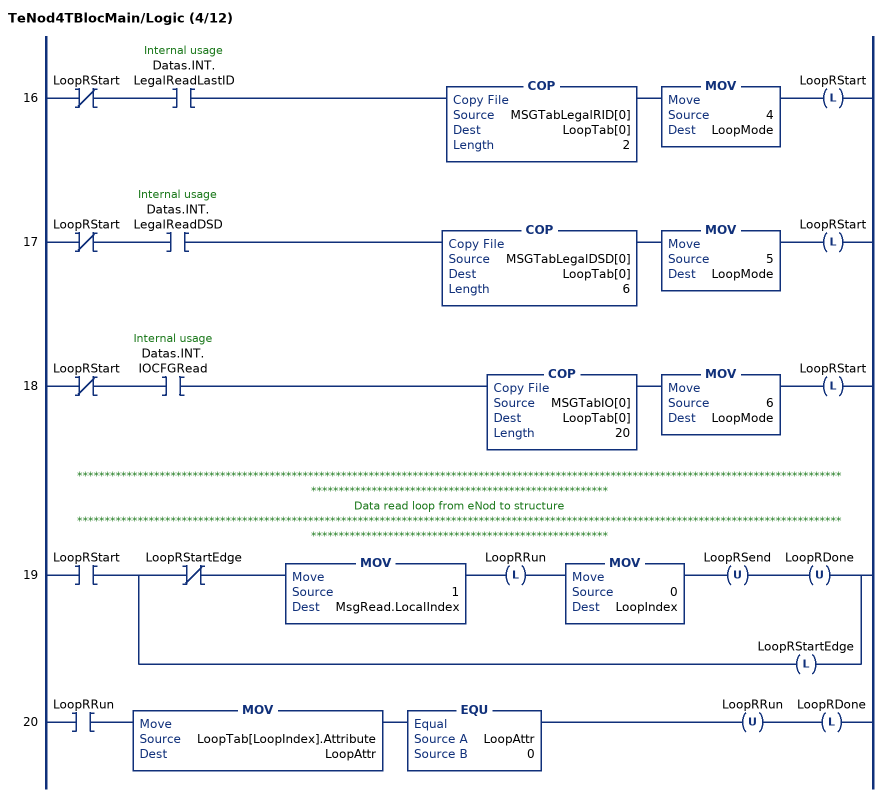
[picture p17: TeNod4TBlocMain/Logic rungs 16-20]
   16: XIO(LoopRStart)XIC(Datas.INT.LegalReadLastID)COP(MSGTabLegalRID[0],LoopTab[0],2)MOV(4,LoopMode)OTL(LoopRStart);
   17: XIO(LoopRStart)XIC(Datas.INT.LegalReadDSD)COP(MSGTabLegalDSD[0],LoopTab[0],6)MOV(5,LoopMode)OTL(LoopRStart);
   18: XIO(LoopRStart)XIC(Datas.INT.IOCFGRead)COP(MSGTabIO[0],LoopTab[0],20)MOV(6,LoopMode)OTL(LoopRStart);
   // *************************************************************************************************************************************************************************************************
   // Data read loop from eNod to structure
   // *************************************************************************************************************************************************************************************************
   19: XIC(LoopRStart)[XIO(LoopRStartEdge) MOV(1,MsgRead.LocalIndex) OTL(LoopRRun) MOV(0,LoopIndex) OTU(LoopRSend) OTU(LoopRDone) ,OTL(LoopRStartEdge) ];
   20: XIC(LoopRRun)MOV(LoopTab[LoopIndex].Attribute,LoopAttr)EQU(LoopAttr,0)OTU(LoopRRun)OTL(LoopRDone);
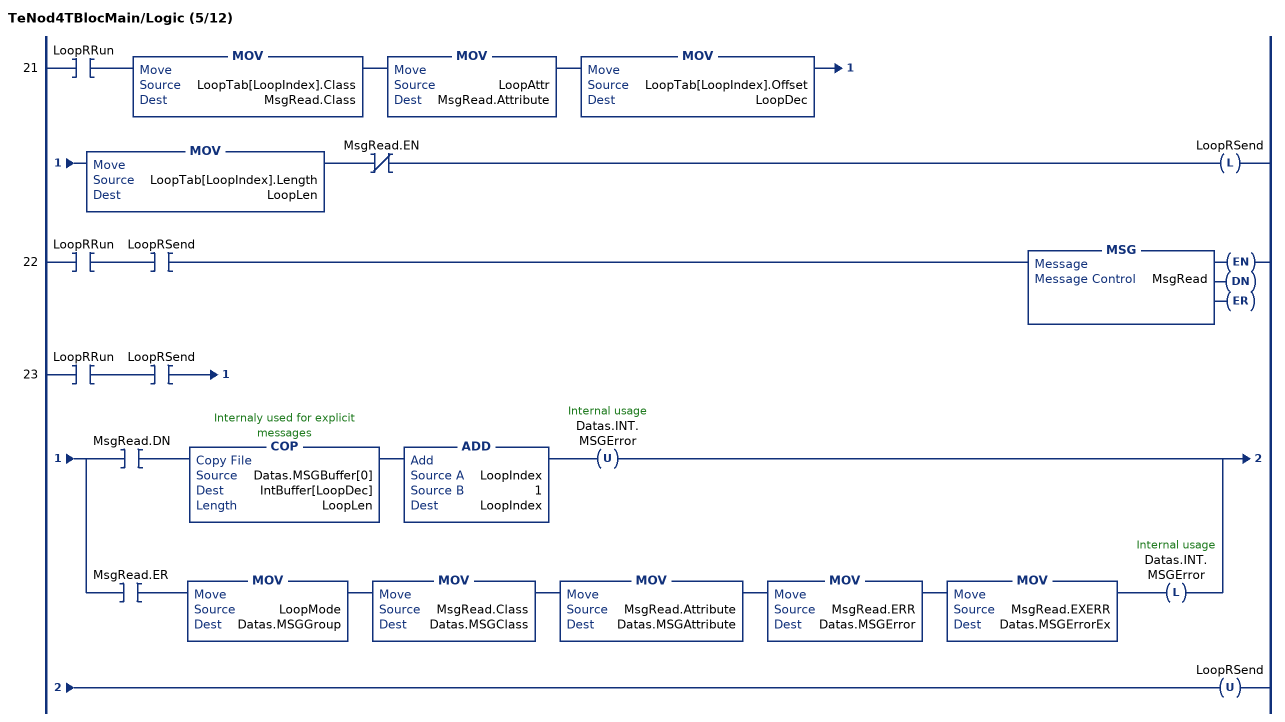
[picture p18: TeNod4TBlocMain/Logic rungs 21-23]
   21: XIC(LoopRRun)MOV(LoopTab[LoopIndex].Class,MsgRead.Class)MOV(LoopAttr,MsgRead.Attribute)MOV(LoopTab[LoopIndex].Offset,LoopDec)MOV(LoopTab[LoopIndex].Length,LoopLen)XIO(MsgRead.EN)OTL(LoopRSend);
   22: XIC(LoopRRun)XIC(LoopRSend)MSG(MsgRead);
   23: XIC(LoopRRun)XIC(LoopRSend)[XIC(MsgRead.DN) COP(Datas.MSGBuffer[0],IntBuffer[LoopDec],LoopLen) ADD(LoopIndex,1,LoopIndex) OTU(Datas.INT.MSGError) ,XIC(MsgRead.ER) MOV(LoopMode,Datas.MSGGroup) MOV(MsgRead.Class,Datas.MSGClass) MOV(MsgRead.Attribute,Datas.MSGAttribute) MOV(MsgRead.ERR,Datas.MSGError) MOV(MsgRead.EXERR,Datas.MSGErrorEx) OTL(Datas.INT.MSGError) ]OTU(LoopRSend);
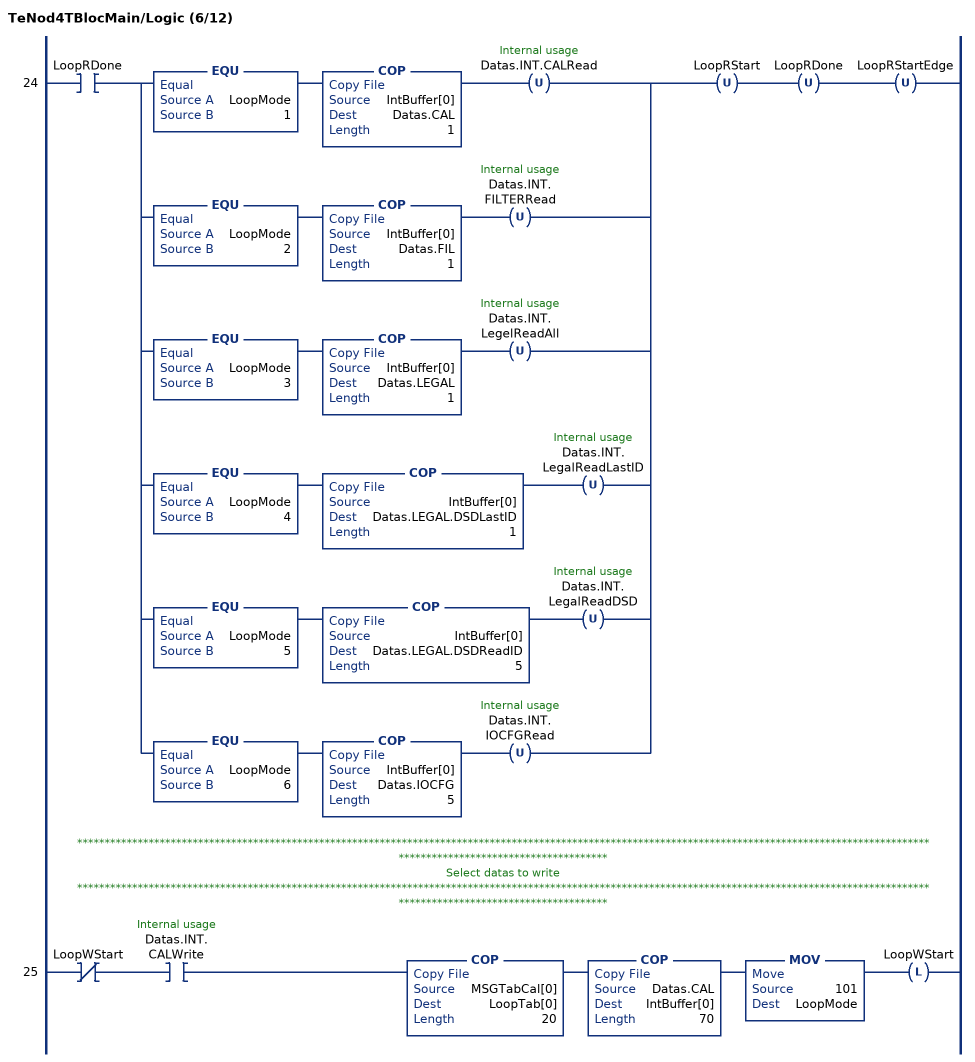
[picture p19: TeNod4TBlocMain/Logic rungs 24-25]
   24: XIC(LoopRDone)[EQU(LoopMode,1) COP(IntBuffer[0],Datas.CAL,1) OTU(Datas.INT.CALRead) ,EQU(LoopMode,2) COP(IntBuffer[0],Datas.FIL,1) OTU(Datas.INT.FILTERRead) ,EQU(LoopMode,3) COP(IntBuffer[0],Datas.LEGAL,1) OTU(Datas.INT.LegelReadAll) ,EQU(LoopMode,4) COP(IntBuffer[0],Datas.LEGAL.DSDLastID,1) OTU(Datas.INT.LegalReadLastID) ,EQU(LoopMode,5) COP(IntBuffer[0],Datas.LEGAL.DSDReadID,5) OTU(Datas.INT.LegalReadDSD) ,EQU(LoopMode,6) COP(IntBuffer[0],Datas.IOCFG,5) OTU(Datas.INT.IOCFGRead) ]OTU(LoopRStart)OTU(LoopRDone)OTU(LoopRStartEdge);
   // *************************************************************************************************************************************************************************************************
   // Select datas to write
   // *************************************************************************************************************************************************************************************************
   25: XIO(LoopWStart)XIC(Datas.INT.CALWrite)COP(MSGTabCal[0],LoopTab[0],20)COP(Datas.CAL,IntBuffer[0],70)MOV(101,LoopMode)OTL(LoopWStart);
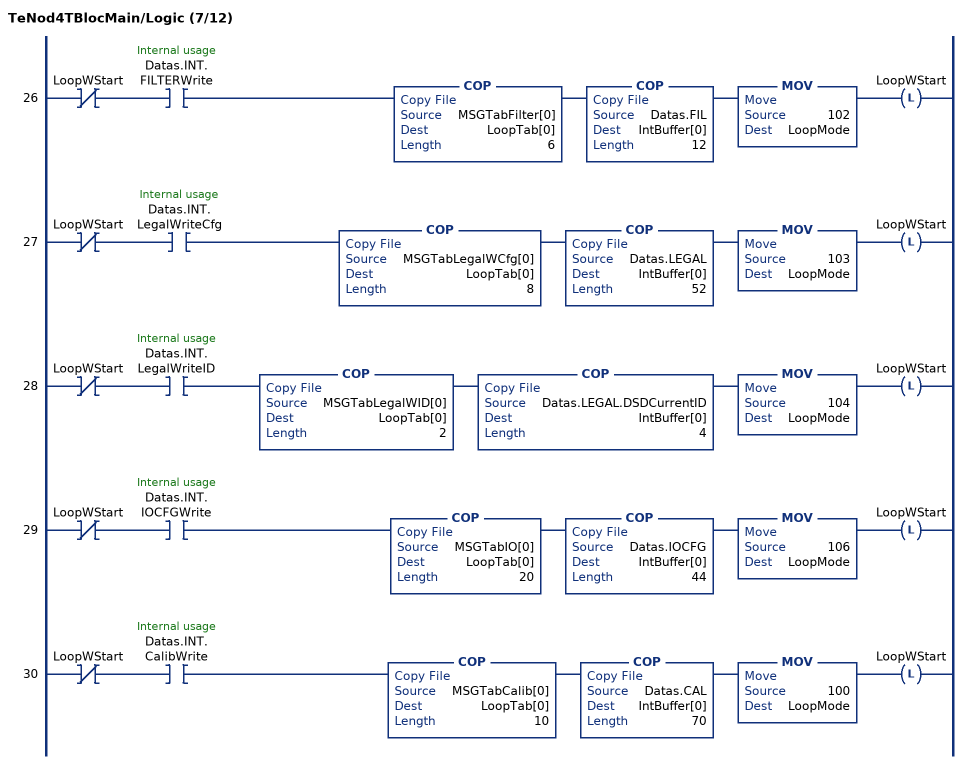
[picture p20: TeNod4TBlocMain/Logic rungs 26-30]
   26: XIO(LoopWStart)XIC(Datas.INT.FILTERWrite)COP(MSGTabFilter[0],LoopTab[0],6)COP(Datas.FIL,IntBuffer[0],12)MOV(102,LoopMode)OTL(LoopWStart);
   27: XIO(LoopWStart)XIC(Datas.INT.LegalWriteCfg)COP(MSGTabLegalWCfg[0],LoopTab[0],8)COP(Datas.LEGAL,IntBuffer[0],52)MOV(103,LoopMode)OTL(LoopWStart);
   28: XIO(LoopWStart)XIC(Datas.INT.LegalWriteID)COP(MSGTabLegalWID[0],LoopTab[0],2)COP(Datas.LEGAL.DSDCurrentID,IntBuffer[0],4)MOV(104,LoopMode)OTL(LoopWStart);
   29: XIO(LoopWStart)XIC(Datas.INT.IOCFGWrite)COP(MSGTabIO[0],LoopTab[0],20)COP(Datas.IOCFG,IntBuffer[0],44)MOV(106,LoopMode)OTL(LoopWStart);
   30: XIO(LoopWStart)XIC(Datas.INT.CalibWrite)COP(MSGTabCalib[0],LoopTab[0],10)COP(Datas.CAL,IntBuffer[0],70)MOV(100,LoopMode)OTL(LoopWStart);
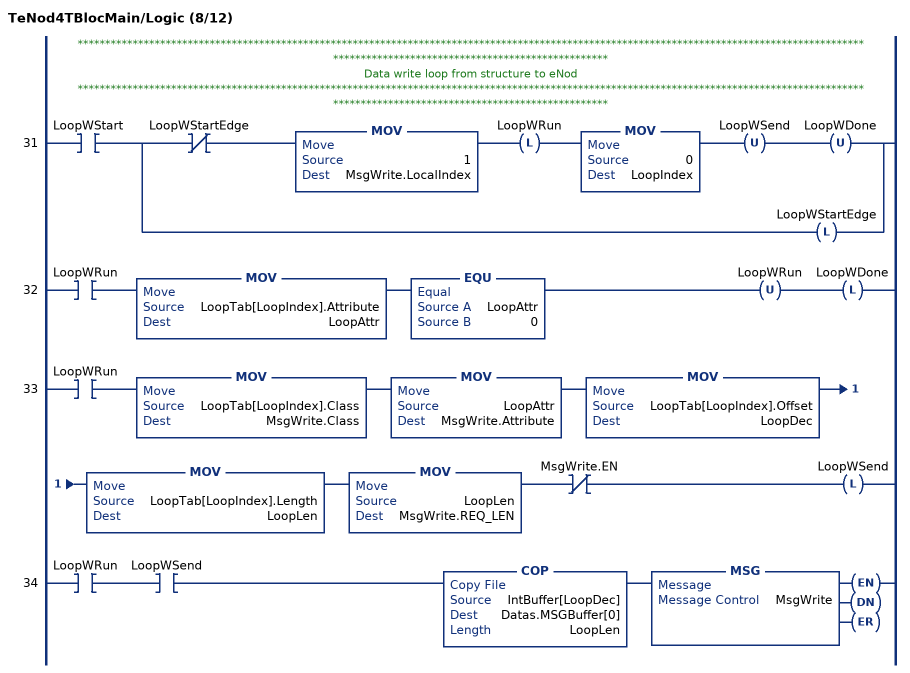
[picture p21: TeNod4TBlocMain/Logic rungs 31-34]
   // *************************************************************************************************************************************************************************************************
   // Data write loop from structure to eNod
   // *************************************************************************************************************************************************************************************************
   31: XIC(LoopWStart)[XIO(LoopWStartEdge) MOV(1,MsgWrite.LocalIndex) OTL(LoopWRun) MOV(0,LoopIndex) OTU(LoopWSend) OTU(LoopWDone) ,OTL(LoopWStartEdge) ];
   32: XIC(LoopWRun)MOV(LoopTab[LoopIndex].Attribute,LoopAttr)EQU(LoopAttr,0)OTU(LoopWRun)OTL(LoopWDone);
   33: XIC(LoopWRun)MOV(LoopTab[LoopIndex].Class,MsgWrite.Class)MOV(LoopAttr,MsgWrite.Attribute)MOV(LoopTab[LoopIndex].Offset,LoopDec)MOV(LoopTab[LoopIndex].Length,LoopLen)MOV(LoopLen,MsgWrite.REQ_LEN)XIO(MsgWrite.EN)OTL(LoopWSend);
   34: XIC(LoopWRun)XIC(LoopWSend)COP(IntBuffer[LoopDec],Datas.MSGBuffer[0],LoopLen)MSG(MsgWrite);
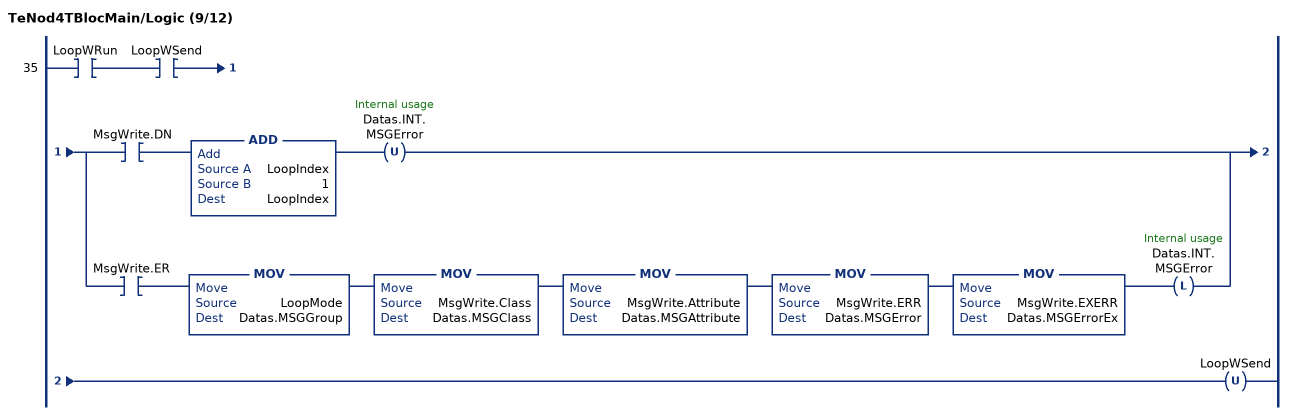
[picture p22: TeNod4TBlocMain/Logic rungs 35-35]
   35: XIC(LoopWRun)XIC(LoopWSend)[XIC(MsgWrite.DN) ADD(LoopIndex,1,LoopIndex) OTU(Datas.INT.MSGError) ,XIC(MsgWrite.ER) MOV(LoopMode,Datas.MSGGroup) MOV(MsgWrite.Class,Datas.MSGClass) MOV(MsgWrite.Attribute,Datas.MSGAttribute) MOV(MsgWrite.ERR,Datas.MSGError) MOV(MsgWrite.EXERR,Datas.MSGErrorEx) OTL(Datas.INT.MSGError) ]OTU(LoopWSend);
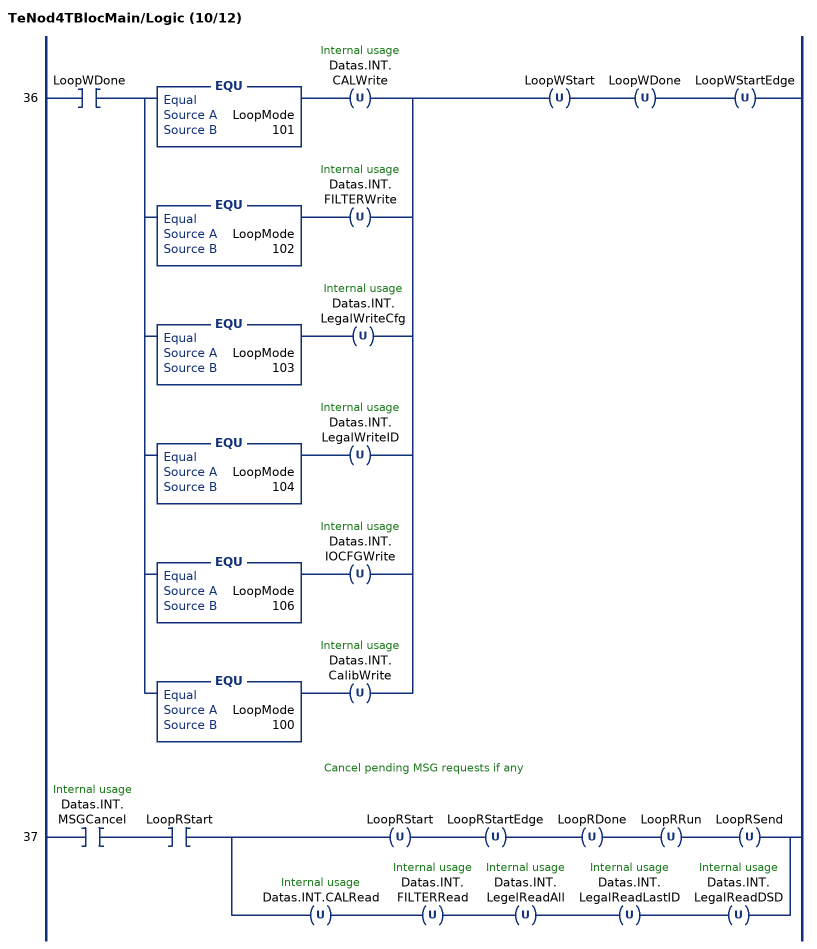
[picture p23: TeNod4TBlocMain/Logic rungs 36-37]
   36: XIC(LoopWDone)[EQU(LoopMode,101) OTU(Datas.INT.CALWrite) ,EQU(LoopMode,102) OTU(Datas.INT.FILTERWrite) ,EQU(LoopMode,103) OTU(Datas.INT.LegalWriteCfg) ,EQU(LoopMode,104) OTU(Datas.INT.LegalWriteID) ,EQU(LoopMode,106) OTU(Datas.INT.IOCFGWrite) ,EQU(LoopMode,100) OTU(Datas.INT.CalibWrite) ]OTU(LoopWStart)OTU(LoopWDone)OTU(LoopWStartEdge);
   // Cancel pending MSG requests if any
   37: XIC(Datas.INT.MSGCancel)XIC(LoopRStart)[OTU(LoopRStart) OTU(LoopRStartEdge) OTU(LoopRDone) OTU(LoopRRun) OTU(LoopRSend) ,OTU(Datas.INT.CALRead) OTU(Datas.INT.FILTERRead) OTU(Datas.INT.LegelReadAll) OTU(Datas.INT.LegalReadLastID) OTU(Datas.INT.LegalReadDSD) ];
